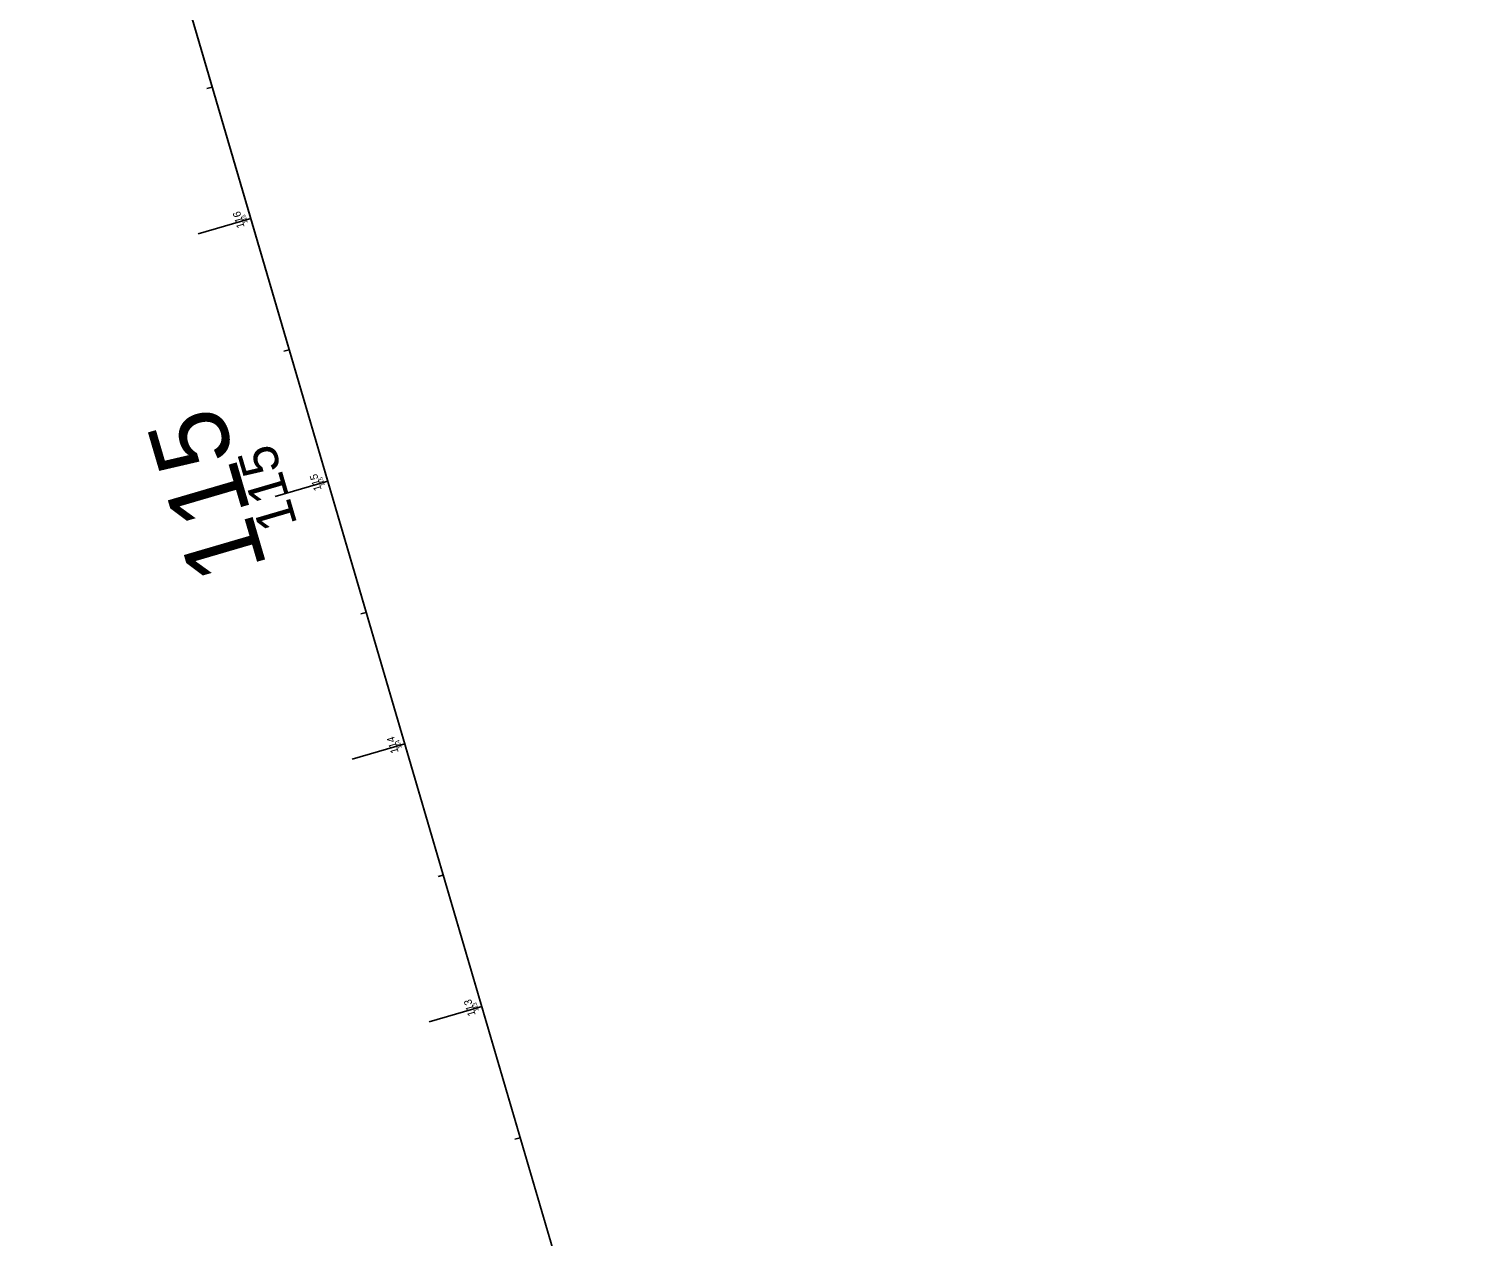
# Model space of a CAD drawing. Extents: x 1794716 to 1797874, y 325521 to 329174.
# Drawn here: x 1796270 to 1796801, y 326876 to 327317 of the extents above; entities that cross this region are included whole.
import ezdxf

# ---------------------------------------------------------------- set-up
doc = ezdxf.new("R2010")
doc.units = 0
for name, color, linetype in [('GE_P_CL_10', 7, 'Continuous'), ('GE_P_CL_100', 7, 'Continuous'), ('GE_P_CL_20', 7, 'Continuous'), ('GE_P_CL_200', 7, 'Continuous'), ('RW_X_CL_20', 7, 'Continuous')]:
    doc.layers.add(name, color=color, linetype=linetype)

msp = doc.modelspace()

# ---------------------------------------------------------------- linework, layer by layer
at = {"layer": 'GE_P_CL_10'}
for p, q in [((1796800.73, 325712.87), (1796269.93, 327524.51)), ((1796336.79, 327296.3), (1796335.83, 327296.02)), ((1796350.85, 327248.32), (1796349.89, 327248.04)), ((1796364.91, 327200.34), (1796363.95, 327200.06)), ((1796378.97, 327152.36), (1796378.01, 327152.07)), ((1796393.03, 327104.37), (1796392.07, 327104.09)), ((1796407.09, 327056.39), (1796406.13, 327056.11)), ((1796421.14, 327008.41), (1796420.19, 327008.13)), ((1796435.2, 326960.42), (1796434.24, 326960.14)), ((1796449.26, 326912.44), (1796448.3, 326912.16))]:
    msp.add_line(p, q, dxfattribs=at)
at = {"layer": 'GE_P_CL_100'}
for p, q in [((1796800.73, 325712.87), (1796269.93, 327524.51)), ((1796350.85, 327248.32), (1796341.25, 327245.51)), ((1796378.97, 327152.36), (1796369.37, 327149.54)), ((1796407.09, 327056.39), (1796397.49, 327053.58)), ((1796435.2, 326960.42), (1796425.61, 326957.61))]:
    msp.add_line(p, q, dxfattribs=at)
at = {"layer": 'GE_P_CL_20'}
for p, q in [((1796800.73, 325712.87), (1796269.93, 327524.51)), ((1796336.79, 327296.3), (1796334.87, 327295.74)), ((1796350.85, 327248.32), (1796348.93, 327247.76)), ((1796364.91, 327200.34), (1796362.99, 327199.78)), ((1796378.97, 327152.36), (1796377.05, 327151.79)), ((1796393.03, 327104.37), (1796391.11, 327103.81)), ((1796407.09, 327056.39), (1796405.17, 327055.83)), ((1796421.14, 327008.41), (1796419.23, 327007.84)), ((1796435.2, 326960.42), (1796433.28, 326959.86)), ((1796449.26, 326912.44), (1796447.34, 326911.88))]:
    msp.add_line(p, q, dxfattribs=at)
at = {"layer": 'GE_P_CL_200'}
for p, q in [((1796800.73, 325712.87), (1796269.93, 327524.51)), ((1796350.85, 327248.32), (1796331.66, 327242.7)), ((1796378.97, 327152.36), (1796359.78, 327146.73)), ((1796407.09, 327056.39), (1796387.89, 327050.77)), ((1796435.2, 326960.42), (1796416.01, 326954.8))]:
    msp.add_line(p, q, dxfattribs=at)
at = {"layer": 'RW_X_CL_20'}
msp.add_lwpolyline([(1796800.73, 325712.87), (1796269.93, 327524.51)], dxfattribs=at)

# ---------------------------------------------------------------- texts
at = {"layer": 'GE_P_CL_10'}
for s, p in [('116', (1796349.75, 327246.75)), ('115', (1796377.87, 327150.79)), ('114', (1796405.98, 327054.84)), ('113', (1796434.1, 326958.85))]:
    msp.add_text(s, height=1.4, rotation=106.3303, dxfattribs=at).set_placement(p)
at = {"layer": 'GE_P_CL_100'}
msp.add_text('115', height=14, rotation=106.3303, dxfattribs=at).set_placement((1796367.93, 327136.67))
at = {"layer": 'GE_P_CL_20'}
for s, p in [('116', (1796348.65, 327245.17)), ('115', (1796376.76, 327149.22)), ('114', (1796404.87, 327053.28)), ('113', (1796433, 326957.28))]:
    msp.add_text(s, height=2.8, rotation=106.3303, dxfattribs=at).set_placement(p)
at = {"layer": 'GE_P_CL_200'}
msp.add_text('115', height=28, rotation=106.3303, dxfattribs=at).set_placement((1796356.9, 327120.98))

doc.saveas('drawing.dxf')
